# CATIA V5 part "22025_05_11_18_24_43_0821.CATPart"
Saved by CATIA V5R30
Part number: 22025_05_11_18_24_43_0821
Definition: 2025_05_11_18_24_43_0821
Nomenclature: 2025_05_11_18_24_43_0821
Source: Unknown
Description: PART-2025_05_11_18_24_43_0821-DESC
Bounding box of the stored display mesh (mm): x 240.75 to 266.25, y -12.75 to 12.75, z 0 to 53
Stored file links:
  E:\Bakalarka\Model\Forma_v7\22025_05_11_18_24_43_0821.CATPart
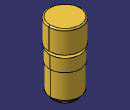
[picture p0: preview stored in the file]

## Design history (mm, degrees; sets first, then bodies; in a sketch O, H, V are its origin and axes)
Body1 "MANIFOLD_SOLID_BREP #148" (main body)
  Solid1: solid without history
